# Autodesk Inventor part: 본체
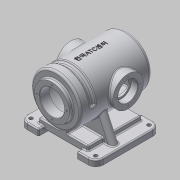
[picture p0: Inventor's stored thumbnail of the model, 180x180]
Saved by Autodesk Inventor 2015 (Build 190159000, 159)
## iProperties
Created: 2015-10
Part Number: 본체
Document SubType Name: Modeling
Designer: mdu
Density: 2.71 g/cm^3
Material: 알루미늄 6061
Mass: 4592.12 g
Surface Area: 2715.66 cm^2
Volume: 1694.51 cm^3
Appearance: 기본값(1)
Author: mdu
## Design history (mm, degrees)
sketch "스케치1"
  geometry: L1 (-100, 85)-(-50, 85); L2 (-50, 85)-(-50, -85); L3 (-50, -85)-(-100, -85); L4 (-100, -85)-(-100, 85); L5 (50, 85)-(100, 85); L6 (100, 85)-(100, -85); L7 (100, -85)-(50, -85); L8 (50, -85)-(50, 85); 3 further points
  constraints: 16 end point, 4 parallel, 2 equal length, 2 horizontal, 2 horizontal alignment, 2 midpoint, 2 perpendicular
  dimensions: "d0" = 100 distance between parallel lines of L8 L2; "d1" = 170 distance of L3.end L1.start; "d3" = 200 distance between parallel lines of L6 L4; "d4" = 50 distance from line of point (0, 0) L2 (= 0.5 x d0)
extrude "돌출1" new body sketch "스케치1" distance "d5" = 16; taper "d6" = 0 deg
node "작업 평면1"
sketch "스케치2"
  geometry: L1 (-65, 70)-(65, 70); L2 (65, 70)-(65, -70); L3 (65, -70)-(-65, -70); L4 (-65, -70)-(-65, 70); 3 further points
  constraints: 8 end point, 2 midpoint, 2 parallel, 1 horizontal, 1 horizontal alignment, 1 perpendicular, 1 vertical alignment
  dimensions: "d8" = 130 distance of L2.end L3.end; "d9" = 140 distance of L1.end L2.end
extrude "돌출2" join sketch "스케치2" distance "d10" = 20; taper "d11" = 0 deg
sketch "스케치3"
  geometry: L1 (-100, 110)-(100, 110); L2 (85, 0)-(-85, 0) reference; L3 (100, 110)-(100, 175); L4 (100, 175)-(-90, 175); L5 (-90, 175)-(-90, 156); L6 (-90, 156)-(-100, 156); L7 (-100, 156)-(-100, 110); L8 (90, 110)-(90, 165); L9 (90, 165)-(-75, 165); L10 (-75, 165)-(-75, 110); L11 (-100, 142.5)-(-75, 142.5); 3 further points
  constraints: 20 end point, 5 perpendicular, 4 parallel, 4 point on line, 2 midpoint, 1 horizontal, 1 vertical alignment
  dimensions: "d12" = 110 distance from line of L2 L1.end; "d13" = 200 distance of L1.start L1.end; "d14" = 130 diameter of L4 L1; "d15" = 92 diameter of L6 L1; "d16" = 10 distance of L5.end L6.end; "d42" = 110 diameter of L9 L1; "d43" = 10 distance between parallel lines of L3 L8; "d44" = 25 distance between parallel lines of L10 L7; "d45" = 65 diameter of L11 L1
revolve "회전1" sketch "스케치3" stored, may be unused: angle "d17" = 90 deg
sketch "스케치4"
  geometry: L1 (-50, 70)-(50, 70) reference; L2 (50, -70)-(-50, -70) reference; L3 (-10, 70)-(-10, -70); L4 (10, -70)-(10, 70); 1 further point
  constraints: 4 end point, 4 point on line, 2 perpendicular
  dimensions: "d18" = 20 distance between parallel lines of L4 L3; "d19" = 10 distance from line of point (0, 0) L3
extrude "돌출3" join sketch "스케치4" stored distance "d20" = 10; taper "d21" = 0 deg
node "작업 평면2"
sketch "스케치5"
  geometry: L1 (-50, -8)-(0, -8) reference; L2 (100, -8)-(150, -8) reference; L3 (-40, -8)-(-8.943, -74.601); L4 (140, -8)-(108.943, -74.601); L5 (-50, 8)-(-50, -8) reference; L6 (150, 8)-(150, -8) reference; A1 r 65 centre (50, -102) between (-8.943, -74.601) and (108.943, -74.601) reference; 1 further point
  constraints: 4 end point, 2 point on circle, 2 point on line, 1 equal length
  dimensions: "d23" = 10 distance from line of L3.start L5; "d24" = 10 distance from line of L4.start L6; "d25" = 25 deg angle of L3 L5
feature "리브1" sketch "스케치5" dims "d26" = 1, "d27" = 20, "d28" = 0
node "작업 평면3"
sketch "스케치6"
  geometry: L1 (100, 156)-(100, 64) reference; C1 r 40 at (-25, 110); 2 further points
  constraints: 1 centre point, 1 horizontal alignment, 1 midpoint
  dimensions: "d37" = 80 diameter of C1; "d38" = 125 distance from line of C1.centre L1
extrude "돌출4" join sketch "스케치6" stored distance "d39" = 10; taper "d40" = 0 deg
hole "구멍1" diameter "d48" = 42; stored, may be unused: countersink angle "d52" = 90 deg, drill point angle "d54" = 118 deg; dims "d46" = 10, "d47" = 10, "d49" = 6, "d50" = 52, "d51" = 18, "d53" = 8
sketch "스케치7"
  geometry: C1 r 40 at (0, 0) reference; 2 further points
  constraints: 1 horizontal alignment
  dimensions: "d55" = 32.5 distance of point (32.5, 0) C1.centre
hole "구멍2" sketch "스케치7" at (32.5, 0) diameter "d56" = 3.242; stored, may be unused: countersink angle "d60" = 90 deg, drill point angle "d62" = 118 deg; dims "d57" = 11, "d58" = 52, "d59" = 18, "d61" = 13
sketch "스케치8"
  geometry: C1 r 46 at (0, 0) reference; 2 further points
  constraints: 1 vertical alignment
  dimensions: "d66" = 39 distance of C1.centre point (0, 39)
hole "구멍3" sketch "스케치8" at (0, 39) diameter "d67" = 3.242; stored, may be unused: countersink angle "d71" = 90 deg, drill point angle "d73" = 118 deg; dims "d68" = 11, "d69" = 52, "d70" = 18, "d72" = 13
fillet "모깎기7" dims "d77" = 20, "d78" = 5, "d79" = 3, "d80" = 10, "d107" = 10
fillet "모깎기8" dims "d81" = 3
fillet "모깎기9" dims "d82" = 3
fillet "모깎기10" dims "d83" = 3, "d84" = 0.3
chamfer "모따기1" distance "d85" = 1; stored, may be unused: second distance "d86" = 2, angle "d87" = 45 deg
node "작업 평면4"
sketch "스케치10"
  geometry: 5 further points
  constraints: 2 horizontal alignment, 2 vertical alignment
  dimensions: "d90" = 170 distance of point (85, 70) point (-85, 70); "d91" = 140 distance of point (-85, 70) point (-85, -70); "d92" = 70 vertical distance of point (0, 0) point (-85, -70) (= 0.5 x d91); "d93" = 85 horizontal distance of point (0, 0) point (-85, 70) (= 0.5 x d90)
hole "구멍4" sketch "스케치10" at (-85, 70), (85, 70), (85, -70), (-85, -70) diameter "d94" = 10; stored, may be unused: countersink angle "d98" = 90 deg, drill point angle "d100" = 118 deg; dims "d95" = 6, "d96" = 4, "d97" = 2, "d99" = 8
node "작업 평면5"
sketch "스케치12" dims "d22" = -90
  geometry: L1 (-65, -90)-(65, -90) reference; L2 (65, 85)-(-65, 85) reference; L3 (0, -90)-(0, 85); 3 further points
  constraints: 3 midpoint, 2 end point, 1 coincident, 1 other
feature "엠보싱3" sketch "스케치12" dims "d105" = 1, "d106" = 0
node "작업축1"
sketch "스케치13"
  geometry: L1 (-85, 175)-(90, 175) reference; L2 (-65, 175)-(-50, 175); L3 (-50, 175)-(-50, 170); L4 (-50, 170)-(-65, 170); L5 (-65, 170)-(-65, 175); L6 (-90, 50)-(-90, 170) reference; L7 (-140, 110)-(140, 110) reference; 1 further point
  constraints: 8 end point, 2 parallel, 1 horizontal, 1 perpendicular, 1 point on line
  dimensions: "d108" = 25 distance between parallel lines of L5 L6; "d109" = 15 distance of L3.end L4.end; "d110" = 5 distance of L2.end L3.end
revolve "회전2" sketch "스케치13" stored, may be unused: angle "d111" = 180 deg
fillet "모깎기11" dims "d112" = 5
fillet "모깎기12" dims "d113" = 5
fillet "모깎기13" dims "d114" = 3
node "솔리드1"
mirror "대칭1"
pattern_circular "원형 패턴1" dims angle "d64" = 360 deg
mirror "대칭3"
pattern_circular "원형 패턴2" dims angle "d75" = 360 deg
other parameters: "d7" = 8, "d36" = -75
